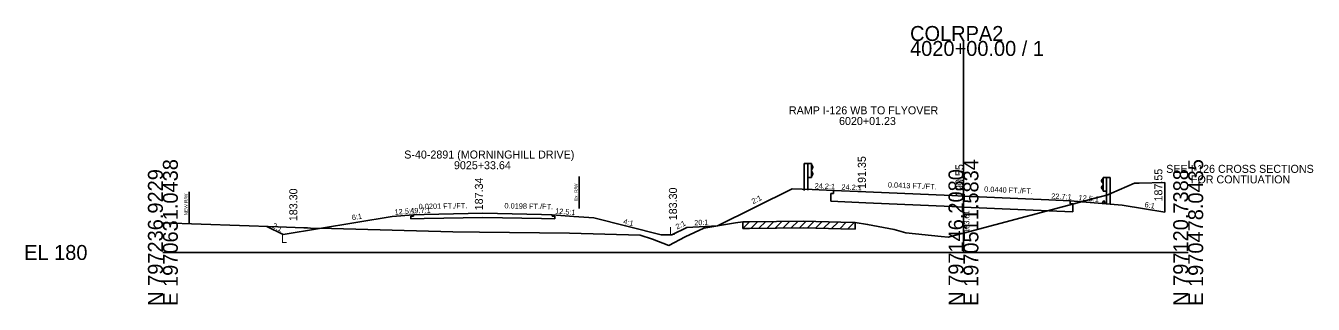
# Model space of a CAD drawing. Extents: x -26 to 1971083, y -10 to 798159.
# Drawn here: x -25.7 to 215.5, y 3990.3 to 4042.5 of the extents above; entities that cross this region are included whole.
import ezdxf

# ---------------------------------------------------------------- set-up
doc = ezdxf.new("R2010")
doc.units = 0
for name, color, linetype in [('RD_GPK_XS_Cell', 7, 'Continuous'), ('RD_XS_Base', 7, 'Continuous'), ('RD_XS_CurbTop', 7, 'Continuous'), ('RD_XS_EarthShd', 7, 'Continuous'), ('RD_XS_ExGround', 7, 'Continuous'), ('RD_XS_ExPaveRet', 7, 'Continuous'), ('RD_XS_ExRW', 7, 'Continuous'), ('RD_XS_GR', 7, 'Continuous'), ('RD_XS_Misc_Line', 7, 'Continuous'), ('RD_XS_NewRW', 7, 'Continuous'), ('RD_XS_Pave', 7, 'Continuous'), ('RD_XS_PaveShd', 7, 'Continuous'), ('RD_XS_TieSlope', 7, 'Continuous'), ('RD_XS_TX_Elev_EX', 7, 'Continuous'), ('RD_XS_TX_Elev_PR', 7, 'Continuous'), ('RD_XS_TX_Misc', 7, 'Continuous'), ('RD_XS_TX_MkPT', 7, 'Continuous'), ('RD_XS_TX_Notes', 7, 'Continuous'), ('RD_XS_TX_Profile', 7, 'Continuous'), ('RD_XS_TX_ShdSlope', 7, 'Continuous'), ('RD_XS_TX_Slope', 7, 'Continuous'), ('RD_XS_TX_Station', 7, 'Continuous')]:
    doc.layers.add(name, color=color, linetype=linetype)

msp = doc.modelspace()

# ---------------------------------------------------------------- linework, layer by layer
at = {"layer": 'RD_GPK_XS_Cell'}
for p, q in [((150, 4000), (150, 4039.61)), ((0, 4000), (150, 4000)), ((150, 4000), (192.11, 4000))]:
    msp.add_line(p, q, dxfattribs=at)
at = {"layer": 'RD_XS_Base'}
for p, q in [((125.17, 4011.06), (125.67, 4011.04)), ((125.17, 4009.58), (125.17, 4011.06)), ((131.71, 4009.31), (125.17, 4009.58)), ((125.67, 4011.04), (125.67, 4011.6)), ((131.71, 4009.31), (147.8, 4008.64)), ((170, 4009.11), (170, 4009.67)), ((46.95, 4006.78), (46.95, 4007.08)), ((72.97, 4006.78), (72.97, 4007.08)), ((147.8, 4008.64), (150, 4008.51)), ((150, 4008.51), (166, 4007.8)), ((166, 4007.8), (170.5, 4007.6)), ((170.5, 4009.08), (170, 4009.11)), ((170.5, 4007.6), (170.5, 4009.08)), ((46.45, 4006.77), (46.95, 4006.78)), ((46.45, 4006.29), (46.45, 4006.77)), ((48.95, 4006.34), (46.45, 4006.29)), ((48.95, 4006.34), (59.96, 4006.56)), ((59.96, 4006.56), (70.97, 4006.34)), ((70.97, 4006.34), (73.47, 4006.29)), ((73.47, 4006.77), (72.97, 4006.78)), ((73.47, 4006.29), (73.47, 4006.77))]:
    msp.add_line(p, q, dxfattribs=at)
at = {"layer": 'RD_XS_CurbTop'}
for p, q in [((176, 4009.19), (176.25, 4009.64)), ((176.47, 4009.15), (176.41, 4009.59)), ((176, 4009.19), (176.47, 4009.15))]:
    msp.add_line(p, q, dxfattribs=at)
msp.add_ellipse((176.32, 4009.56), major_axis=(0, -0.131), ratio=0.686, start_param=1.762783, end_param=4.036677, dxfattribs=at)
at = {"layer": 'RD_XS_EarthShd'}
for p, q in [((125.67, 4011.6), (121.65, 4011.77)), ((170, 4009.67), (176, 4009.19)), ((46.95, 4007.08), (42.94, 4006.76)), ((72.97, 4007.08), (76.97, 4006.76))]:
    msp.add_line(p, q, dxfattribs=at)
at = {"layer": 'RD_XS_ExGround'}
msp.add_lwpolyline([(0, 4005.55), (21.53, 4004.8), (26.43, 4004.63), (27.1, 4004.6), (27.63, 4004.58), (31.62, 4004.48), (54.3, 4003.88), (59.35, 4003.82), (76.21, 4003.61), (89.43, 4003.26), (91.74, 4002.5), (94.79, 4001.31), (97.85, 4002.92), (101.33, 4004.55), (107.3, 4005.54), (108.67, 4005.75), (109.92, 4005.76), (120.01, 4005.88), (127.05, 4005.69), (129.72, 4005.62), (132.05, 4005.27), (137.01, 4004.33), (139.2, 4003.67), (145.82, 4002.98), (147.13, 4002.85), (150, 4003.61), (174.41, 4010.08), (177.04, 4010.78), (177.72, 4011.08), (182.03, 4012.96), (182.93, 4012.98), (187.75, 4013.1)], dxfattribs=at)
at = {"layer": 'RD_XS_ExPaveRet'}
for p, q in [((108.67, 4004.5), (108.67, 4005.75)), ((108.67, 4004.5), (109.92, 4004.51)), ((109.92, 4004.51), (120.01, 4004.63)), ((120.01, 4004.63), (127.05, 4004.44)), ((129.72, 4005.62), (129.72, 4004.37)), ((127.05, 4004.44), (129.72, 4004.37))]:
    msp.add_line(p, q, dxfattribs=at)
at = {"layer": 'RD_XS_ExRW'}
msp.add_line((77.99, 4014.24), (77.99, 4008.24), dxfattribs=at)
at = {"layer": 'RD_XS_GR'}
for p, q in [((120.83, 4016.64), (120.16, 4016.64)), ((120.16, 4016.64), (120.16, 4011.59)), ((121.5, 4016.64), (120.83, 4016.64)), ((120.83, 4016.64), (120.83, 4011.7)), ((121.5, 4014.07), (121.5, 4016.64)), ((121.5, 4016.48), (121.77, 4016.04)), ((121.77, 4015.93), (121.5, 4015.49)), ((121.77, 4014.78), (121.5, 4015.22)), ((121.5, 4014.23), (121.77, 4014.67)), ((121.77, 4016.04), (121.77, 4015.93)), ((121.77, 4014.67), (121.77, 4014.78)), ((121.5, 4014.07), (120.83, 4014.07)), ((176.15, 4013.9), (175.88, 4013.46)), ((175.88, 4013.46), (175.88, 4013.35)), ((175.88, 4013.35), (176.15, 4012.91)), ((175.88, 4012.2), (176.15, 4012.64)), ((175.88, 4012.09), (175.88, 4012.2)), ((176.15, 4011.65), (175.88, 4012.09)), ((176.15, 4014.06), (176.81, 4014.06)), ((176.15, 4011.49), (176.15, 4014.06)), ((176.81, 4014.06), (177.48, 4014.06)), ((176.81, 4014.06), (176.81, 4009.12)), ((177.48, 4014.06), (177.48, 4009.01)), ((176.15, 4011.49), (176.81, 4011.49))]:
    msp.add_line(p, q, dxfattribs=at)
at = {"layer": 'RD_XS_Misc_Line'}
for p, q in [((108.67, 4004.5), (109.94, 4005.76)), ((110.18, 4004.51), (111.46, 4005.78)), ((111.69, 4004.53), (112.97, 4005.8)), ((113.2, 4004.55), (114.48, 4005.81)), ((114.71, 4004.57), (115.99, 4005.83)), ((116.23, 4004.59), (117.5, 4005.85)), ((117.74, 4004.61), (119.01, 4005.87)), ((119.25, 4004.62), (120.5, 4005.87)), ((120.76, 4004.61), (121.98, 4005.83)), ((122.27, 4004.57), (123.5, 4005.79)), ((123.78, 4004.53), (125.01, 4005.74)), ((125.29, 4004.49), (126.52, 4005.7)), ((126.81, 4004.44), (128.03, 4005.66)), ((128.32, 4004.41), (129.55, 4005.63))]:
    msp.add_line(p, q, dxfattribs=at)
at = {"layer": 'RD_XS_NewRW'}
msp.add_line((4.91, 4011.38), (4.91, 4005.38), dxfattribs=at)
at = {"layer": 'RD_XS_Pave'}
for p, q in [((131.71, 4011.35), (147.8, 4010.68)), ((147.8, 4010.68), (150, 4010.55)), ((150, 4010.55), (166, 4009.84)), ((48.95, 4007.12), (59.96, 4007.34)), ((59.96, 4007.34), (70.97, 4007.12))]:
    msp.add_line(p, q, dxfattribs=at)
at = {"layer": 'RD_XS_PaveShd'}
for p, q in [((131.71, 4011.35), (125.67, 4011.6)), ((166, 4009.84), (170, 4009.67)), ((48.95, 4007.12), (46.95, 4007.08)), ((70.97, 4007.12), (72.97, 4007.08))]:
    msp.add_line(p, q, dxfattribs=at)
at = {"layer": 'RD_XS_TieSlope'}
for p, q in [((117.88, 4011.92), (103.89, 4004.97)), ((121.65, 4011.77), (117.88, 4011.92)), ((187.75, 4007.55), (187.75, 4013.1)), ((176, 4009.19), (179.75, 4008.89)), ((179.75, 4008.89), (187.75, 4007.55)), ((22.52, 4003.36), (19.49, 4004.87)), ((42.94, 4006.76), (22.52, 4003.36)), ((76.97, 4006.76), (80.72, 4006.46)), ((80.72, 4006.46), (93.37, 4003.3)), ((98.14, 4004.68), (95.37, 4003.3)), ((98.14, 4004.68), (103.89, 4004.97)), ((93.37, 4003.3), (95.37, 4003.3))]:
    msp.add_line(p, q, dxfattribs=at)

# ---------------------------------------------------------------- texts
at = {"layer": 'RD_GPK_XS_Cell'}
for s, p in [('COLRPA2', (140, 4039.61)), ('4020+00.00 / 1', (140, 4036.81)), ('EL 180', (-26, 3998.6))]:
    msp.add_text(s, height=2.8, dxfattribs=at).set_placement(p)
for s, p in [('E 1970631.0438', (2.8, 3990)), ('E 1970511.5834', (152.8, 3990)), ('E 1970478.0435', (194.91, 3990)), ('N 797236.9229', (0, 3990)), ('N 797146.2080', (150, 3990)), ('N 797120.7388', (192.11, 3990))]:
    msp.add_text(s, height=2.8, rotation=90, dxfattribs=at).set_placement(p)
at = {"layer": 'RD_XS_ExRW'}
msp.add_text('Ex. R/W ', height=0.65, rotation=90, dxfattribs=at).set_placement((77.74, 4009.62))
at = {"layer": 'RD_XS_NewRW'}
msp.add_text('NEW R/W ', height=0.65, rotation=90, dxfattribs=at).set_placement((4.64, 4006.94))
at = {"layer": 'RD_XS_TX_Elev_EX'}
msp.add_text('183.61', height=1, rotation=90, dxfattribs=at).set_placement((151.11, 4003.68))
at = {"layer": 'RD_XS_TX_Elev_PR'}
for s, p in [(' 191.35', (131.71, 4011.35)), (' 190.55', (150, 4009.84)), (' 187.34', (59.96, 4007.34))]:
    msp.add_text(s, height=1.5, rotation=90, dxfattribs=at).set_placement(p)
at = {"layer": 'RD_XS_TX_Misc'}
for s, p in [('187.55', (187.27, 4009.55)), ('183.30', (25.19, 4005.86)), ('183.30', (96.31, 4006.03))]:
    msp.add_text(s, height=1.5, rotation=90, dxfattribs=at).set_placement(p)
at = {"layer": 'RD_XS_TX_MkPT'}
for p in [(94.87, 4003.3), (22.13, 4001.79)]:
    msp.add_text('L', height=1.5, dxfattribs=at).set_placement(p)
at = {"layer": 'RD_XS_TX_Notes'}
for s, p in [('SEE I-126 CROSS SECTIONS', (187.99, 4014.91)), ('FOR CONTIUATION', (192.62, 4012.94))]:
    msp.add_text(s, height=1.5, dxfattribs=at).set_placement(p)
at = {"layer": 'RD_XS_TX_Profile'}
msp.add_text('49.7:1', height=1, rotation=1.1522, dxfattribs=at).set_placement((46.36, 4007.32))
at = {"layer": 'RD_XS_TX_ShdSlope'}
for s, rotation, p in [('24.2:1', 357.6349, (122.09, 4012)), ('12.5:1', 355.4261, (171.54, 4009.79)), ('12.5:1', 4.5697, (43.45, 4007.05)), ('12.5:1', 355.4323, (73.46, 4007.29))]:
    msp.add_text(s, height=1, rotation=rotation, dxfattribs=at).set_placement(p)
at = {"layer": 'RD_XS_TX_Slope'}
for s, rotation, p in [('24.2:1', 357.6349, (127.12, 4011.79)), ('0.0413 FT./FT.', 357.6349, (135.82, 4012.18)), ('0.0440 FT./FT.', 357.4806, (153.86, 4011.38)), ('0.0201 FT./FT.', 1.1522, (47.93, 4008.1)), ('2:1', 26.4277, (110.6, 4009.04)), ('22.7:1', 357.4806, (166.43, 4010.07)), ('6:1', 350.5377, (183.88, 4008.51)), ('6:1', 9.4537, (35.48, 4006.02)), ('0.0198 FT./FT.', 358.8649, (63.99, 4008.26)), ('2:1', 333.4561, (20.39, 4004.7)), ('4:1', 345.9638, (86.19, 4005.38)), ('2:1', 26.5651, (96.36, 4004.29)), ('20:1', 2.8624, (99.57, 4005.06))]:
    msp.add_text(s, height=1, rotation=rotation, dxfattribs=at).set_placement(p)
at = {"layer": 'RD_XS_TX_Station'}
for s, p in [('RAMP I-126 WB TO FLYOVER', (117.3, 4025.87)), ('6020+01.23', (126.69, 4023.87)), ('S-40-2891 (MORNINGHILL DRIVE)', (45.22, 4017.59)), ('9025+33.64', (54.54, 4015.59))]:
    msp.add_text(s, height=1.5, dxfattribs=at).set_placement(p)

doc.saveas('drawing.dxf')
